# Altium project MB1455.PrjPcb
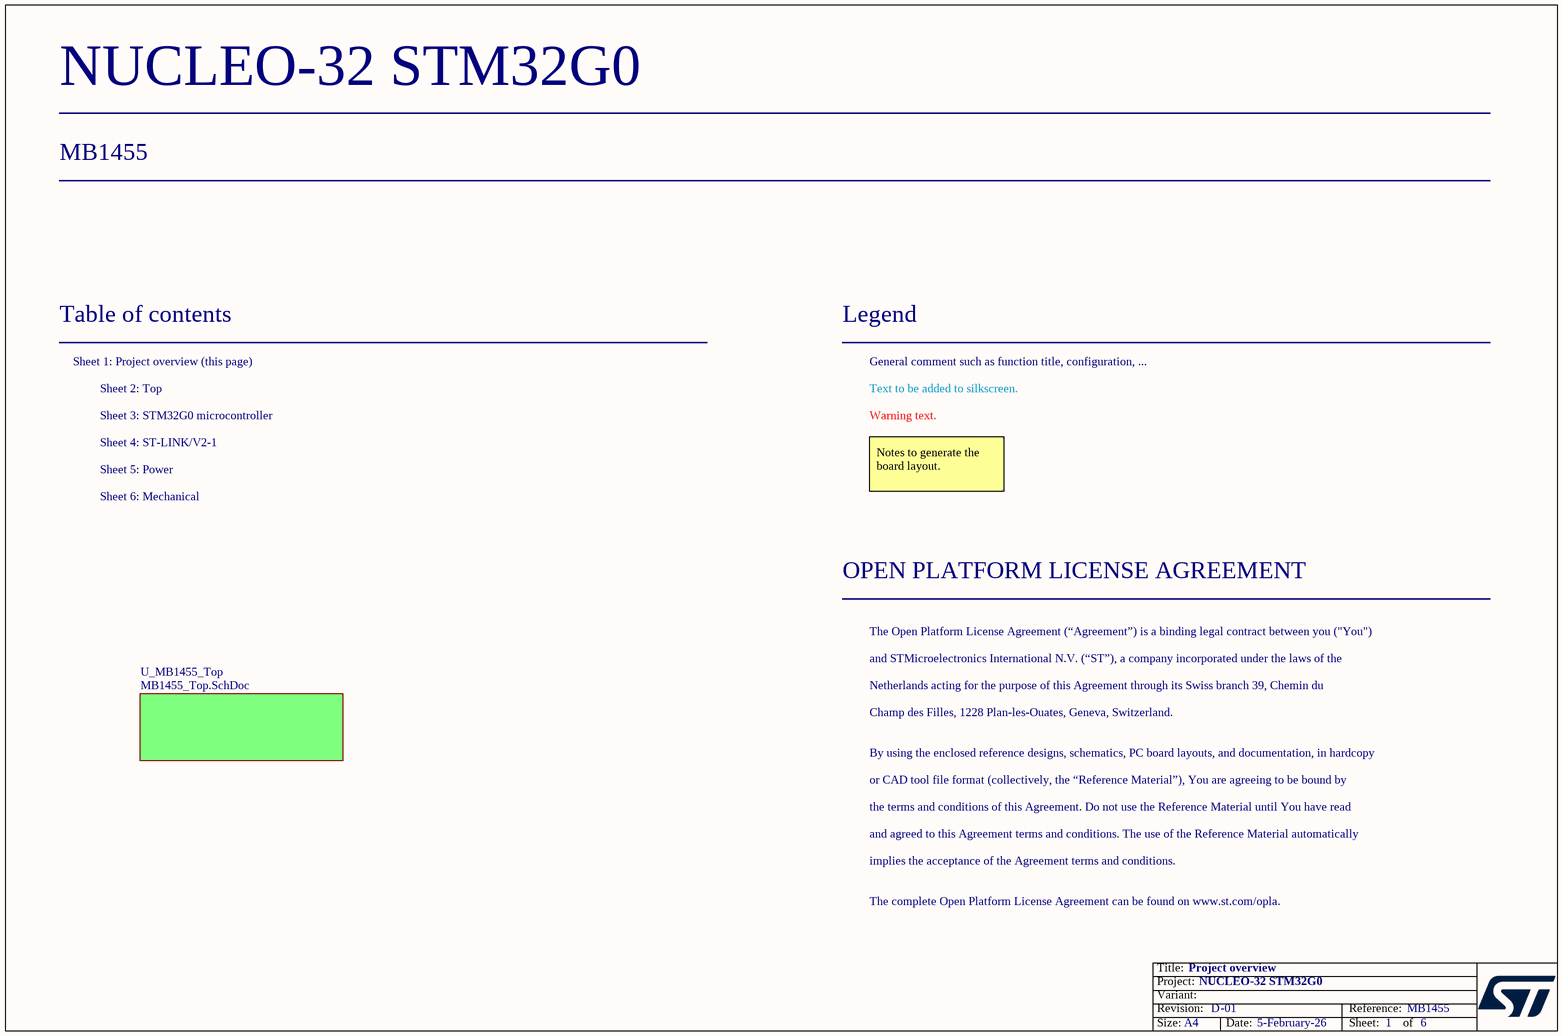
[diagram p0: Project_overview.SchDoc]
Board_Assembly_Revision: 01; Board_Document_Date: 5-February-26; Board_Name: NUCLEO-32 STM32G0; Board_PCB_Revision: D; Board_Reference: MB1455
6 sheets, 97 parts. Net scope: flat (ports and power ports of the same name join across sheets).
Board file: MB1455.PcbDoc
Sheets:
  Project_overview.SchDoc
    U_MB1455_Top = MB1455_Top.SchDoc
      U_Power = Power.SchDoc
      Mechanical = Mechanical.SchDoc
      U_ST_LINK_V2-1 = ST_LINK_V2-1.SCHDOC
      U_STM32G0_microcontroller = STM32G0_microcontroller.SchDoc

## Sheet Project_overview.SchDoc: Project overview
size A4; Date: Not used; ApprovedBy: Not used; CheckedBy: Not used; Author: Not used; CompanyName: STMicroelectronics; DrawnBy: Not used; Engineer: Not used; Organization: Not used; Address1: Not used; Address2: Not used; Address3: Not used; Address4: Not used; DocumentNumber: Not used; Revision: Not used; SheetNumber: 1; SheetTotal: 6

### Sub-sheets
U_MB1455_Top = MB1455_Top.SchDoc: no entries

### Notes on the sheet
- Table of contents
- Sheet 1: Project overview (this page)
- Legend
- General comment such as function title, configuration, ...
- Sheet 2: Top
- Sheet 4: ST-LINK/V2-1
- Sheet 3: STM32G0 microcontroller
- Text to be added to silkscreen.
- Warning text.
- Sheet 5: Power
- Sheet 6: Mechanical
- Notes to generate the board layout.
- OPEN PLATFORM LICENSE AGREEMENT
- The Open Platform License Agreement (“Agreement”) is a binding legal contract between you ("You")
- and STMicroelectronics International N.V. (“ST”), a company incorporated under the laws of the
- Netherlands acting for the purpose of this Agreement through its Swiss branch 39, Chemin du
- Champ des Filles, 1228 Plan-les-Ouates, Geneva, Switzerland.
- By using the enclosed reference designs, schematics, PC board layouts, and documentation, in hardcopy
- or CAD tool file format (collectively, the “Reference Material”), You are agreeing to be bound by
- the terms and conditions of this Agreement. Do not use the Reference Material until You have read
- and agreed to this Agreement terms and conditions. The use of the Reference Material automatically
- implies the acceptance of the Agreement terms and conditions.
- The complete Open Platform License Agreement can be found on www.st.com/opla.

## Sheet MB1455_Top.SchDoc: Top hierarchical view
size A4; Date: Not used; ApprovedBy: Not used; CheckedBy: Not used; Author: Not used; CompanyName: STMicroelectronics; DrawnBy: Not used; Engineer: Not used; Organization: Not used; Address1: Not used; Address2: Not used; Address3: Not used; Address4: Not used; DocumentNumber: Not used; Revision: A-01-P3; SheetNumber: 2; SheetTotal: 6
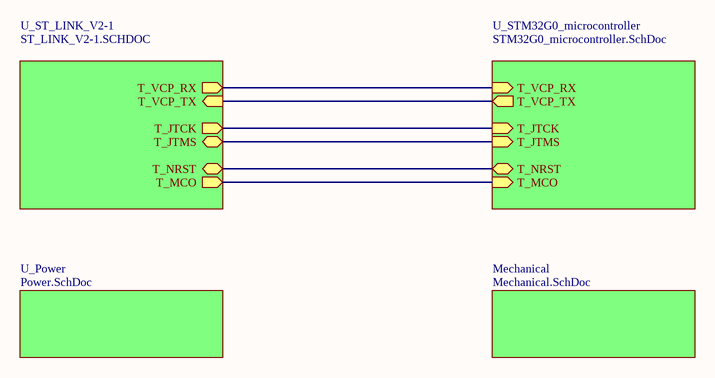
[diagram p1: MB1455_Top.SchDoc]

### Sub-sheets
Mechanical = Mechanical.SchDoc: no entries
U_Power = Power.SchDoc: no entries
U_ST_LINK_V2-1 = ST_LINK_V2-1.SCHDOC: T_VCP_RX (out), T_VCP_TX (in), T_JTMS (bidir), T_JTCK (out), T_NRST (bidir), T_MCO (out)
U_STM32G0_microcontroller = STM32G0_microcontroller.SchDoc: T_NRST (bidir), T_JTCK (in), T_JTMS (in), T_VCP_RX (in), T_VCP_TX (out), T_MCO (in)

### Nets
(unnamed): sheet U_ST_LINK_V2-1/T_VCP_RX, sheet U_STM32G0_microcontroller/T_VCP_RX
(unnamed): sheet U_ST_LINK_V2-1/T_VCP_TX, sheet U_STM32G0_microcontroller/T_VCP_TX  [a separate net that carries the same name]
(unnamed): sheet U_ST_LINK_V2-1/T_JTMS, sheet U_STM32G0_microcontroller/T_JTMS  [a separate net that carries the same name]
(unnamed): sheet U_ST_LINK_V2-1/T_JTCK, sheet U_STM32G0_microcontroller/T_JTCK  [a separate net that carries the same name]
(unnamed): sheet U_ST_LINK_V2-1/T_NRST, sheet U_STM32G0_microcontroller/T_NRST  [a separate net that carries the same name]
(unnamed): sheet U_ST_LINK_V2-1/T_MCO, sheet U_STM32G0_microcontroller/T_MCO  [a separate net that carries the same name]

## Sheet Power.SchDoc: Power
size A4; Date: Not used; ApprovedBy: Not used; CheckedBy: Not used; Author: Not used; CompanyName: STMicroelectronics; DrawnBy: Not used; Engineer: Not used; Organization: Not used; Address1: Not used; Address2: Not used; Address3: Not used; Address4: Not used; DocumentNumber: Not used; Revision: Not used; SheetNumber: 5; SheetTotal: 6
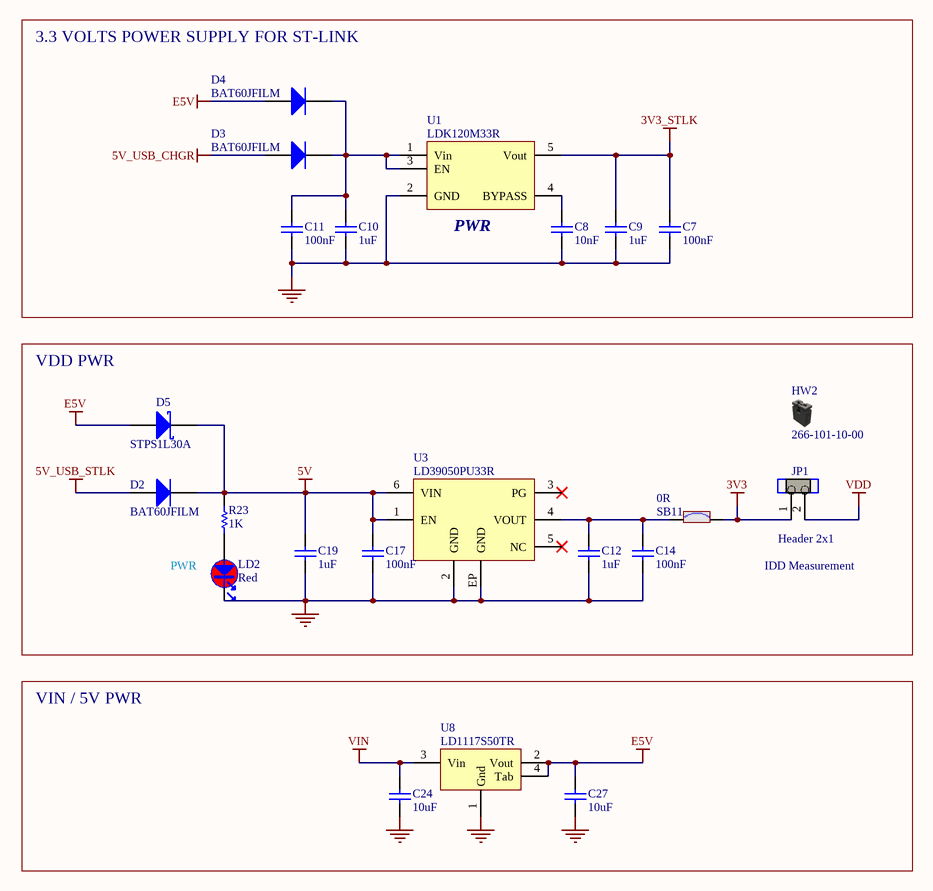
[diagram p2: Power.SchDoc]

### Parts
C7  value 100nF  [C0402]  (hidden comment: Capacitor)
C8  value 10nF  [C0402]  (hidden comment: Capacitor)
C9  value 1uF  [C0402]  (hidden comment: Capacitor)
C10  value 1uF  [C0402]  (hidden comment: Capacitor)
C11  value 100nF  [C0402]  (hidden comment: Capacitor)
C12  value 1uF  [C0402]  (hidden comment: Capacitor)
C14  value 100nF  [C0402]  (hidden comment: Capacitor)
C17  value 100nF  [C0402]  (hidden comment: Capacitor)
C19  value 1uF  [C0402]  (hidden comment: Capacitor)
C24  value 10uF  [C0805]  (hidden comment: Capacitor)
C27  value 10uF  [C0805]  (hidden comment: Capacitor)
D2  BAT60JFILM  [DIO_SOD323]
D3  BAT60JFILM  [DIO_SOD323]
D4  BAT60JFILM  [DIO_SOD323]
D5  value STPS1L30A  [DIO_SMA_1A_2K]  (hidden comment: STPS1L40M)
HW2  value 266-101-10-00  (hidden comment: Shunt Black 1.27mm 266-101-10-00)  (mechanical)
JP1  value Header 2x1  [CON_WP_707-2-02-2-20-00]  (hidden comment: Jumper_Header1.27 2x1 Fitted)
LD2  value Red  [LED_0603_VISHAY_VLMS1300-GS08_RED_1A2K_H0P8]  (hidden comment: LED_red)
R23  value 1K  [R0402]  (hidden comment: Resistor)
SB11  value 0R  [SOLDER-BRIDGE_R0603-0R]  (hidden comment: SB_ON)
U1  LDK120M33R  [REG_SOT23-5L]
U3  LD39050PU33R  [ICC_DFN6-EPAD_3X3_P095]
U8  LD1117S50TR  [REG_SOT223-TAB]

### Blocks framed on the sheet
VDD PWR: C12 C14 C17 C19 D2 D5 HW2 JP1 LD2 R23 SB11 U3
VIN / 5V PWR: C24 C27 U8

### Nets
3V3: JP1.1 SB11.2
3V3_STLK: C7.2 C9.2 U1.5(Vout)
5V: C17.2 C19.2 D2.2(K) D5.2(K) R23.2 U3.1(EN) U3.6(VIN)
5V_USB_CHGR: D3.1(A)
5V_USB_STLK: D2.1(A)
E5V: C27.2 D4.1(A) D5.1(A) U8.2(Vout) U8.4(Tab)
GND: C7.1 C8.1 C9.1 C10.1 C11.1 C12.1 C14.1 C17.1 C19.1 C24.1 C27.1 LD2.2 U1.2(GND) U3.2(GND) U3.EP(GND) U8.1(Gnd)
VDD: JP1.2
VIN: C24.2 U8.3(Vin)
NetC8_2: C8.2 U1.4(BYPASS)
NetC10_2: C10.2 C11.2 D3.2(K) D4.2(K) U1.1(Vin) U1.3(EN)
NetC12_2: C12.2 C14.2 SB11.1 U3.4(VOUT)
NetLD2_1: LD2.1 R23.1

Not connected (* = marked no-connect by the designer): U3 3(PG)* 5(NC)*

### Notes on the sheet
- 3.3 VOLTS POWER SUPPLY FOR ST-LINK
- (near U1) PWR
- PWR
- IDD Measurement

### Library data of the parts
C7 C11 C14 C17 = MCD-00006: Capacitor, MLCC, 100nF, 16V, X7R, +/-10%, 0402, T=0.5mm; Manufacturer_Part_Number: CC0402KRX7R7BB104; Manufacturer: YAGEO; Part_Preference: Recommended; Partial_Alternate_Internal_Part_Number: MCD-03299; Component_Country_Of_Origin: China; ID: 2474; Order_Code_RS: 9402047; ShowFields: YES
C8 = MCD-00011: Capacitor, MLCC, 10nF, 16V, X7R, 10%, 0402, T=0.5mm; Manufacturer_Part_Number: CC0402KRX7R7BB103; Manufacturer: YAGEO; Part_Preference: Recommended; Provided_By: SUBCO; ECCN_US: EAR99; ECCN_EU: NEC; Component_Country_Of_Origin: China; ID: 2469; Order_Code_RS: 3019275; ShowFields: YES
C9 C10 C12 C19 = MCD-00095: Capacitor, MLCC, 1uF, 6V3, X5R, 10%, 0402, T=0,5mm; Manufacturer_Part_Number: GRM155R61E105KA12; Manufacturer: MURATA; Alternate_Manufacturer_Part_Number: GRM155R60J105KE19; Part_Preference: Recommended; Partial_Alternate_Internal_Part_Number: MCD-04188; Provided_By: SUBCO; ECCN_US: EAR99; ECCN_EU: NEC; Component_Country_Of_Origin: Japan°°; ID: 2772; Order_Code_RS: 2218855; ShowFields: YES
C24 C27 = MCD-00014: Capacitor, MLCC, 10uF, 25V, X5R, 10%, 0805, T=0,85mm; Manufacturer_Part_Number: CC0805KRX5R8BB106; Manufacturer: YAGEO; Full_Alternate_Internal_Part_Number: MCD-02385; Part_Preference: Recommended; Partial_Alternate_Internal_Part_Number: MCD-03053; Provided_By: SUBCO; ECCN_US: EAR99; ECCN_EU: NEC; Component_Country_Of_Origin: China; ID: 2468; ShowFields: YES
D2-D4 = MCD-00034: Part_Type: Diode; Manufacturer: STMICROELECTRONICS; BMS_Part_Number: 9151097; Manufacturer_HQ_COO: EU; Part_Preference: Recommended; ECCN_US: EAR99; ECCN_EU: NEC; Provided_By: SUBCO with ST control; Component_Country_Of_Origin: China; ID: 2483; Order_Code_RS: 714-6879; ShowFields: YES
D5 = MCD-01059: LOW DROP POWER SCHOTTKY RECTIFIER 1A 30V VF=0.3V; Part_Type: Diode; Manufacturer: STMICROELECTRONICS; BMS_Part_Number: 9151096; Manufacturer_HQ_COO: EU; Part_Preference: Recommended; Provided_By: SUBCO with ST control; ECCN_US: EAR99; ECCN_EU: NEC; Component_Country_Of_Origin: China; ID: 2966; Order_Code_RS: 485-8061; ShowFields: YES
HW2 = MCD-01409: SHUNT 1.27mm BLACK; Part_Type: Misc; Manufacturer: W&P PRODUCTS; Alternate_Manufacturer_Part_Number: M50-1900005; Alternate_Manufacturer: HARWIN; Manufacturer_HQ_COO: Unknown; Part_Preference: Recommended; Partial_Alternate_Internal_Part_Number: MCD-04276; Provided_By: SUBCO; Component_Country_Of_Origin: China; ID: 3509; ShowFields: YES
JP1 = MCD-01428: Header, 2x1, 1,27mm, Right Angled, Single Row, Height 3.05mm/1.27mm; Part_Type: Connector; Manufacturer_Part_Number: 707-2-02-2-20-00; Manufacturer: W&P PRODUCTS; Part_Preference: Recommended; Partial_Alternate_Internal_Part_Number: MCD-04275; Provided_By: SUBCO; Component_Country_Of_Origin: China; ID: 3528; ShowFields: YES
LD2 = MCD-02787: LED, Red, 1V7 to 2V2, 5mA, 0603; Manufacturer_Part_Number: 19-217/R6C-AL1M2VY/6T; Manufacturer: EVERLIGHT; Part_Type: Display; Part_Preference: Recommended; Full_Alternate_Internal_Part_Number: MCD-02401; Partial_Alternate_Internal_Part_Number: MCD-00586; Component_Country_Of_Origin: China; ID: 4899; ShowFields: YES
R23 = MCD-00061: Resistor,1K,0402,1%,1/16W; Manufacturer_Part_Number: RC0402FR-071KL; Manufacturer: YAGEO; Part_Preference: Recommended; Provided_By: SUBCO; ECCN_US: EAR99; ECCN_EU: NEC; Component_Country_Of_Origin: China; ID: 2532; Order_Code_RS: 9239235; ShowFields: YES
SB11 = MCD-00071: Solder Bridge ON; Part_Type: Resistor; Manufacturer_Part_Number: RC0603JR-070RL; Manufacturer: YAGEO; Manufacturer_HQ_COO: Unknown; Part_Preference: Recommended; Provided_By: SUBCO; Component_Country_Of_Origin: China; ID: 2521; Order_Code_RS: 199-5647; ShowFields: YES
U1 = MCD-00663: 200 mA low quiescent current very low noise LDO; Part_Type: IC; Manufacturer: STMICROELECTRONICS; BMS_Part_Number: 9176330; Manufacturer_HQ_COO: EU; Part_Preference: Recommended; Partial_Alternate_Internal_Part_Number: MCD-03279; ECCN_US: EAR99; ECCN_EU: NEC; Provided_By: SUBCO with ST control; Component_Country_Of_Origin: China; ID: 3082; Order_Code_RS: 188-9202; ShowFields: YES
U3 = MCD-00215: Low quiescent current and low noise voltage regulators; Manufacturer: STMICROELECTRONICS; Part_Type: IC; BMS_Part_Number: 9176126; Part_Preference: Recommended; Provided_By: SUBCO with ST control; ECCN_US: EAR99; ECCN_EU: NEC; Component_Country_Of_Origin: Malaysia; ID: 2654; Order_Code_RS: 196-1948; ShowFields: YES
U8 = MCD-00088: IC REG LDO 5V 0.8A SOT223; Manufacturer: STMICROELECTRONICS; BMS_Part_Number: 9176133; Manufacturer_HQ_COO: EU; Part_Preference: Recommended; Provided_By: SUBCO with ST control; ECCN_US: EAR99; ECCN_EU: NEC; Component_Country_Of_Origin: China; ID: 2503; Order_Code_RS: 165-7748; ShowFields: YES

## Sheet Mechanical.SchDoc: Mechanical
size A4; Date: Not used; ApprovedBy: Not used; CheckedBy: Not used; Author: Not used; CompanyName: STMicroelectronics; DrawnBy: Not used; Engineer: Not used; Organization: Not used; Address1: Not used; Address2: Not used; Address3: Not used; Address4: Not used; DocumentNumber: Not used; Revision: Not used; SheetNumber: 6; SheetTotal: 6
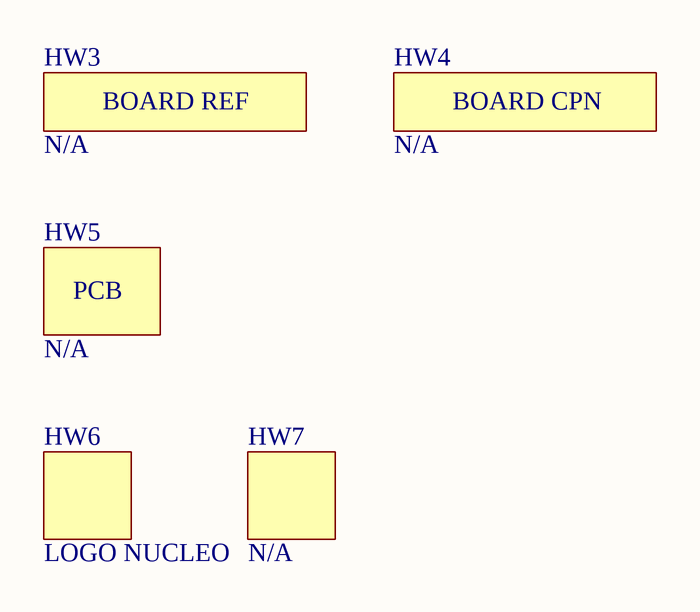
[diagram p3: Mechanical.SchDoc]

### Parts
HW3  STICKER_BOARD_REF  [STICKER_25X9]  (value not drawn)  (no BOM)
HW4  STICKER_BOARD_CPN  [STICKER_25X9]  (value not drawn)  (no BOM)
HW5  PCB  (value not drawn)  (no BOM)
HW6  value LOGO NUCLEO  [LOGO_NUCLEO]  (hidden comment: Logo)  (no BOM)
HW7  Logo  [LOGO_ST]  (value not drawn)  (no BOM)

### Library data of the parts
HW3 = MCD-00235: Sticker to mention board reference + serial number; Part_Type: Misc; Part_Preference: Recommended; Provided_By: SUBCO; Component_Country_Of_Origin: Unknown; ID: 2632; ShowFields: YES
HW4 = MCD-00547: Sticker to mention board CPN code; Part_Type: Misc; Part_Preference: Recommended; Provided_By: SUBCO; Component_Country_Of_Origin: Unknown; ID: 3197; ShowFields: YES
HW5 = MCD-00216: PCB, xxxx for PCB number, Y for PCB revision; Part_Type: Misc; Part_Preference: Forbidden; Provided_By: SUBCO; Component_Country_Of_Origin: Unknown; ID: 2653; ShowFields: YES
HW6 = MCD-00636: NUCLEO logo footprint for PCB; Part_Type: Accessory; Part_Preference: Forbidden; Component_Country_Of_Origin: Unknown; ID: 3110; ShowFields: YES
HW7 = MCD-00625: STMicroelectronics logo footprint for PCB; Part_Type: Misc; Part_Preference: Forbidden; Component_Country_Of_Origin: Unknown; ID: 3117; ShowFields: YES

## Sheet ST_LINK_V2-1.SCHDOC: ST_LINK_V2-1
size A4; Date: Not used; ApprovedBy: Not used; CheckedBy: Not used; Author: Not used; CompanyName: STMicroelectronics; DrawnBy: Not used; Engineer: Not used; Organization: Not used; Address1: Not used; Address2: Not used; Address3: Not used; Address4: Not used; DocumentNumber: Not used; Revision: Not used; SheetNumber: 4; SheetTotal: 6
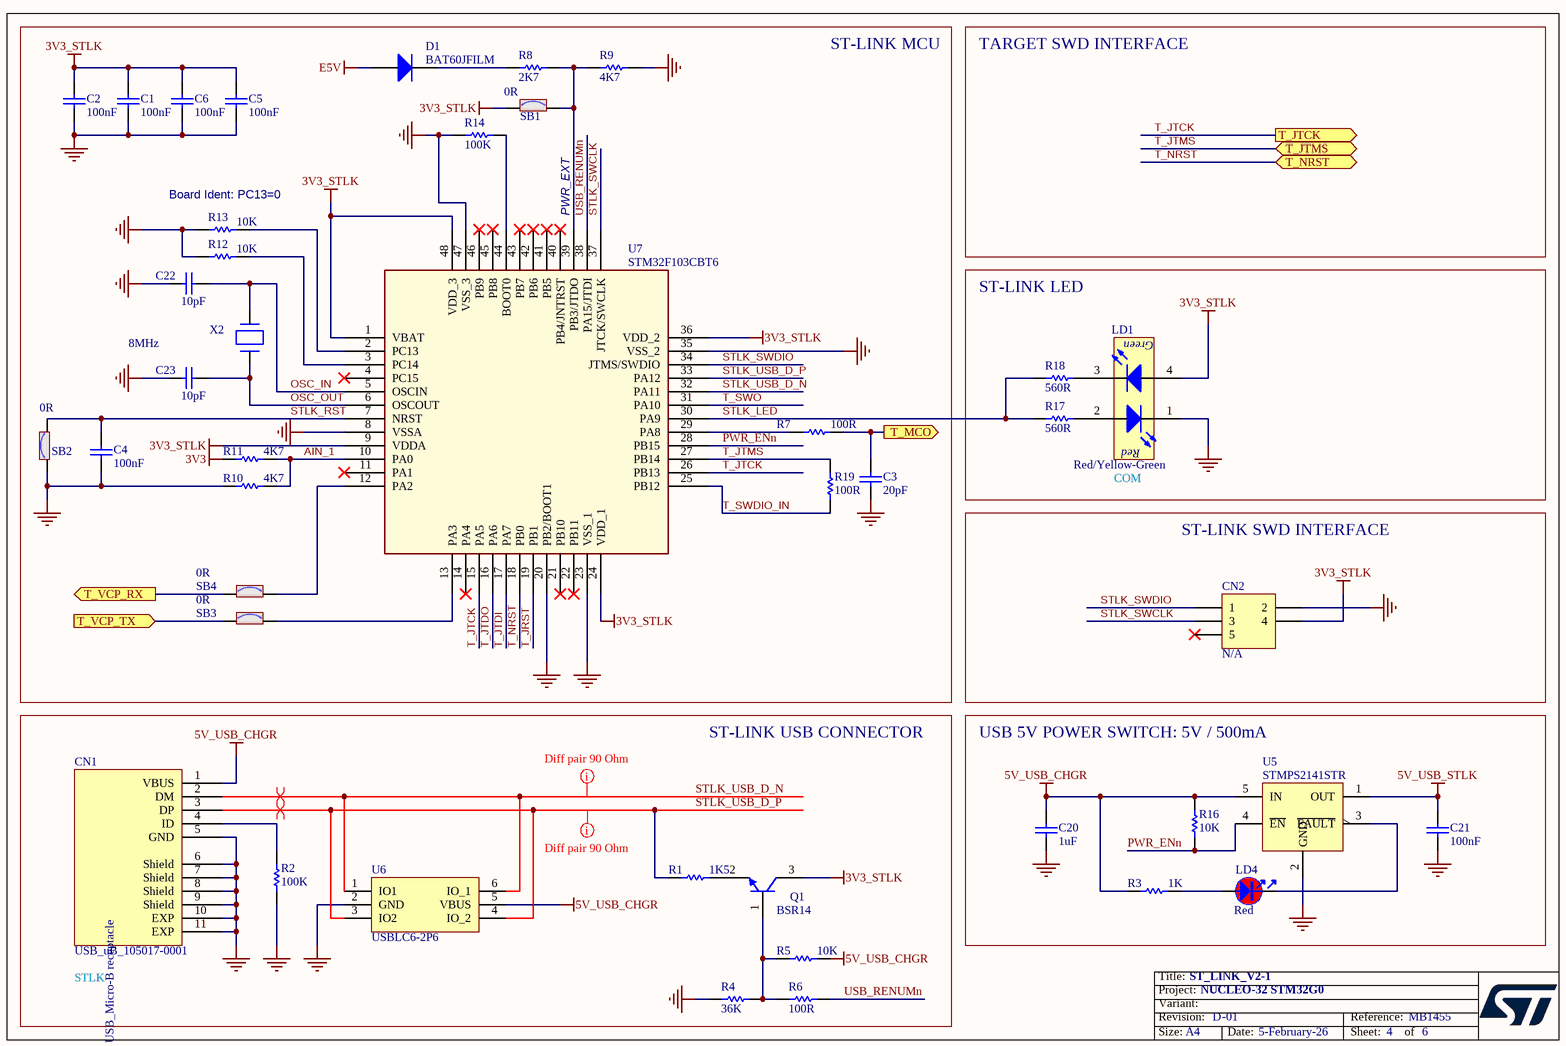
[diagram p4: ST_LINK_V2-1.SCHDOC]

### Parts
C1  value 100nF  [C0402]  (hidden comment: Capacitor)
C2  value 100nF  [C0402]  (hidden comment: Capacitor)
C3  value 20pF  [C0402]  (hidden comment: Capacitor)
C4  value 100nF  [C0402]  (hidden comment: Capacitor)
C5  value 100nF  [C0402]  (hidden comment: Capacitor)
C6  value 100nF  [C0402]  (hidden comment: Capacitor)
C20  value 1uF  [C0402]  (hidden comment: Capacitor)
C21  value 100nF  [C0402]  (hidden comment: Capacitor)
C22  value 10pF  [C0402]  (hidden comment: Capacitor)
C23  value 10pF  [C0402]  (hidden comment: Capacitor)
CN1  value USB_uB_105017-0001  [CON_USBMICROB_MOLEX_105017-0001_H2P90]  (hidden comment: USB_uB_105017.0001)
CN2  Header STLINK  [HDR_1x5_2R54_V_M]  (value not drawn)
D1  BAT60JFILM  [DIO_SOD323]
LD1  value Red/Yellow-Green  [LED_BI-GR_HSMF-A201-A00J1]  (hidden comment: LD_BICOLOR_CMS)
LD4  value Red  [LED_0603_VISHAY_VLMS1300-GS08_RED_1A2K_H0P8]  (hidden comment: LED_red)
Q1  value BSR14  [NPN_SOT23]  (hidden comment: 9013-SOT23)
R1  value 1K5  [R0402]  (hidden comment: Resistor)
R2  value 100K  [R0402]  (hidden comment: Resistor)
R3  value 1K  [R0402]  (hidden comment: Resistor)
R4  value 36K  [R0402]  (hidden comment: Resistor)
R5  value 10K  [R0402]  (hidden comment: Resistor)
R6  value 100R  [R0402]  (hidden comment: Resistor)
R7  value 100R  [R0402]  (hidden comment: Resistor)
R8  value 2K7  [R0402]  (hidden comment: Resistor)
R9  value 4K7  [R0402]  (hidden comment: Resistor)
R10  value 4K7  [R0402]  (hidden comment: Resistor)
R11  value 4K7  [R0402]  (hidden comment: Resistor)
R12  value 10K  [R0402]  (hidden comment: Resistor)
R13  value 10K  [R0402]  (hidden comment: Resistor)
R14  value 100K  [R0402]  (hidden comment: Resistor)
R16  value 10K  [R0402]  (hidden comment: Resistor)
R17  value 560R  [R0402]  (hidden comment: Resistor)
R18  value 560R  [R0402]  (hidden comment: Resistor)
R19  value 100R  [R0402]  (hidden comment: Resistor)
SB1  value 0R  [SOLDER-BRIDGE_R0603-0R]  (hidden comment: SB_ON)
SB2  value 0R  [SOLDER-BRIDGE_R0603-0R]  (hidden comment: SB_ON)
SB3  value 0R  [SOLDER-BRIDGE_R0603-0R]  (hidden comment: SB_ON)
SB4  value 0R  [SOLDER-BRIDGE_R0603-0R]  (hidden comment: SB_ON)
U5  STMPS2141STR  [MOS_SOT23-5L]
U6  USBLC6-2P6  [ESD_SOT666]
U7  STM32F103CBT6  [ICC_LQFP48_7X7_P050]
X2  value 8MHz  [CRY_NX3225GD_2P]  (hidden comment: XTAL_2_PINS)

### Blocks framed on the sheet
ST-LINK MCU: C1-C6 C22 C23 D1 R7-R14 R19 SB1-SB4 U7 X2
ST-LINK LED: LD1 R17 R18
ST-LINK SWD INTERFACE: CN2
ST-LINK USB CONNECTOR: CN1 Q1 R1 R2 R4-R6 U6
USB 5V POWER SWITCH: 5V / 500mA: C20 C21 LD4 R3 R16 U5

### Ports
T_JTCK (out), T_JTMS (bidir), T_MCO (out), T_NRST (bidir), T_VCP_RX (out), T_VCP_TX (in)

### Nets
3V3: R11.1
3V3_STLK: C1.2 C2.2 C5.2 C6.2 CN2.4 LD1.4(YellowGreen_anode) Q1.3(C) SB1.1 U7.1(VBAT) U7.9(VDDA) U7.24(VDD_1) U7.36(VDD_2) U7.48(VDD_3)
5V_USB_CHGR: C20.2 CN1.1(VBUS) R3.1 R5.2 R16.2 U5.5(IN) U6.5(VBUS)
5V_USB_STLK: C21.2 U5.1(OUT)
E5V: D1.1(A)
GND: C1.1 C2.1 C3.1 C4.1 C5.1 C6.1 C20.1 C21.1 C22.1 C23.1 CN1.5(GND) CN1.6(Shield) CN1.7(Shield) CN1.8(Shield) CN1.9(Shield) CN1.10(EXP) CN1.11(EXP) CN2.2 LD1.1(RED_cathode) R2.1 R4.1 R9.2 R10.1 R12.1 R13.1 R14.1 SB2.1 U5.2(GND) U6.2(GND) U7.8(VSSA) U7.20(PB2/BOOT1) U7.23(VSS_1) U7.35(VSS_2) U7.47(VSS_3)
AIN_1: R10.2 R11.2 U7.10(PA0)
OSC_IN: C22.2 U7.5(OSCIN) X2.1(X1)
OSC_OUT: C23.2 U7.6(OSCOUT) X2.2(X2)
PWR_ENn: R16.1 U5.4(~{EN}) U7.28(PB15)
STLK_LED: R17.1 R18.1 U7.30(PA9)
STLK_RST: C4.2 SB2.2 U7.7(NRST)
STLK_SWCLK: CN2.3 U7.37(JTCK/SWCLK)
STLK_SWDIO: CN2.1 U7.34(JTMS/SWDIO)
STLK_USB_D_N: CN1.2(DM) U6.1(IO1) U6.6(IO_1) U7.32(PA11)
STLK_USB_D_P: CN1.3(DP) R1.1 U6.3(IO2) U6.4(IO_2) U7.33(PA12)
T_JRST: U7.19(PB1)
T_JTCK: U7.15(PA5) U7.26(PB13) ; port T_JTCK
T_JTDI: U7.17(PA7)
T_JTDO: U7.16(PA6)
T_JTMS: R19.2 U7.27(PB14) ; port T_JTMS
T_NRST: U7.18(PB0) ; port T_NRST
T_SWDIO_IN: R19.1 U7.25(PB12)
T_SWO: U7.31(PA10)
USB_RENUMn: R6.2 U7.38(PA15/JTDI)
NetC3_2: C3.2 R7.2 ; port T_MCO
NetCN1_4: CN1.4(ID) R2.2
NetD1_2: D1.2(K) R8.1
NetLD1_2: LD1.2(Red_anode) R17.2
NetLD1_3: LD1.3(YellowGreen_cathode) R18.2
NetLD4_1: LD4.1 R3.2
NetLD4_2: LD4.2 U5.3(~{FAULT})
NetQ1_1: Q1.1(B) R4.2 R5.1 R6.1
NetQ1_2: Q1.2(E) R1.2
NetR7_1: R7.1 U7.29(PA8)
NetR8_2: R8.2 R9.1 SB1.2 U7.39(PB3/JTDO)
NetR12_2: R12.2 U7.3(PC14)
NetR13_2: R13.2 U7.2(PC13)
NetR14_2: R14.2 U7.44(BOOT0)
NetSB3_1: SB3.1 ; port T_VCP_TX
NetSB3_2: SB3.2 U7.13(PA3)
NetSB4_1: SB4.1 ; port T_VCP_RX
NetSB4_2: SB4.2 U7.12(PA2)

Not connected (* = marked no-connect by the designer): CN2 5*; U7 4(PC15)* 11(PA1)* 14(PA4)* 21(PB10)* 22(PB11)* 40(PB4/JNTRST)* 41(PB5)* 42(PB6)* 43(PB7)* 45(PB8)* 46(PB9)*

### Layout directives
differential pair: STLK_USB_D_N, STLK_USB_D_P
mark named Diff pair 90 Ohm: STLK_USB_D_N, STLK_USB_D_P

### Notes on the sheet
- TARGET SWD INTERFACE
- (near R13) Board Ident: PC13=0
- PWR_EXT
- COM
- STLK

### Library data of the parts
C1 C2 C4-C6 C21 = MCD-00006: as C7 on sheet Power
C3 = MCD-00016: Capacitor, MLCC, 20pF, 50V, NPO, 5%, 0402, T=0,5mm; Manufacturer_Part_Number: CC0402JRNPO9BN200; Manufacturer: YAGEO; Part_Preference: Recommended; Provided_By: SUBCO; ECCN_US: EAR99; ECCN_EU: NEC; Component_Country_Of_Origin: China; ID: 2479; ShowFields: YES
C20 = MCD-00095: as C9 on sheet Power
C22 C23 = MCD-00015: Capacitor, MLCC, 10pF, 50V, NPO, 5%, 0402, T=0,5mm; Manufacturer_Part_Number: CC0402JRNPO9BN100; Manufacturer: YAGEO; Part_Preference: Recommended; Provided_By: SUBCO; ECCN_US: EAR99; ECCN_EU: NEC; Component_Country_Of_Origin: China; ID: 2465; Order_Code_RS: 3019160RL; ShowFields: YES
CN1 = MCD-00028: USB-MICRO-B, 0.65mm, RA, SMT, Bottom Mount,; Part_Type: Connector; Manufacturer_Part_Number: 1050170001; Manufacturer: MOLEX; Part_Preference: Recommended; Partial_Alternate_Internal_Part_Number: MCD-04277; Provided_By: SUBCO; Component_Country_Of_Origin: Unknown; ID: 2489; Order_Code_RS: 2293836; ShowFields: YES
CN2 = MCD-01399: Header 5 pads for ST-LINK prog. Not fitted; Part_Type: Misc; Part_Preference: Forbidden; Provided_By: SUBCO; Component_Country_Of_Origin: Unknown; ID: 3499; ShowFields: YES
D1 = MCD-00034: Manufacturer: STMICROELECTRONICS; Part_Type: Diode; BMS_Part_Number: 9151097; Manufacturer_HQ_COO: EU; Part_Preference: Recommended; ECCN_US: EAR99; ECCN_EU: NEC; Provided_By: SUBCO with ST control; Component_Country_Of_Origin: China; ID: 2483; Order_Code_RS: 714-6879; ShowFields: YES
LD1 = MCD-02402: LED Bicolor, Red/Yellow-Green , 2V, 20mA, 4-PLCC; Part_Type: Display; Manufacturer_Part_Number: 67-22SURSYGC/S530-A2/TR8; Manufacturer: EVERLIGHT; Full_Alternate_Internal_Part_Number: MCD-00051, MCD-02631; Part_Preference: Not recommended; ID: 4508; ShowFields: YES
LD4 = MCD-02787: LED, Red, 1V7 to 2V2, 5mA, 0603; Part_Type: Display; Manufacturer_Part_Number: 19-217/R6C-AL1M2VY/6T; Manufacturer: EVERLIGHT; Part_Preference: Recommended; Full_Alternate_Internal_Part_Number: MCD-02401; Partial_Alternate_Internal_Part_Number: MCD-00586; Component_Country_Of_Origin: China; ID: 4899; ShowFields: YES
Q1 = MCD-00073: NPN Bipolar Transistor; Manufacturer: ON SEMICONDUCTOR; Alternate_Manufacturer_Part_Number: MMBT2222LT1G / MMBT2222ALT1G / MMBT2222ALT3G; Part_Preference: Recommended; Partial_Alternate_Internal_Part_Number: MCD-01737, MCD-03305, MCD-02988; ECCN_US: EAR99; ECCN_EU: NEC; Provided_By: SUBCO; Component_Country_Of_Origin: Unknown; ID: 2519; ShowFields: YES
R1 = MCD-00068: Resistor,1K5,0402,1%,1/16W; Manufacturer_Part_Number: RC0402FR-071K5L; Manufacturer: YAGEO; Part_Preference: Recommended; Provided_By: SUBCO; ECCN_US: EAR99; ECCN_EU: NEC; Component_Country_Of_Origin: China; ID: 2524; Order_Code_RS: 9239251; ShowFields: YES
R2 R14 = MCD-00059: Resistor,100K,0402,1%,1/16W; Manufacturer_Part_Number: RC0402FR-07100KL; Manufacturer: YAGEO; Alternate_Manufacturer_Part_Number: RT0402FRE07100KL; Part_Preference: Recommended; Partial_Alternate_Internal_Part_Number: MCD-03301; Provided_By: SUBCO; ECCN_US: EAR99; ECCN_EU: NEC; Component_Country_Of_Origin: China; ID: 2533; Order_Code_RS: 2421891; ShowFields: YES
R3 = MCD-00061: as R23 on sheet Power
R4 = MCD-00069: Resistor,36K,0402,1%,1/16W; Manufacturer_Part_Number: RC0402FR-0736KL; Manufacturer: YAGEO; Part_Preference: Recommended; Provided_By: SUBCO; ECCN_US: EAR99; ECCN_EU: NEC; Component_Country_Of_Origin: China; ID: 2523; Order_Code_RS: 1458788; ShowFields: YES
R5 R12 R13 R16 = MCD-00053: Resistor,10K,0402,1%,1/16W; Manufacturer_Part_Number: RC0402FR-0710KL; Manufacturer: YAGEO; BMS_Part_Number: 9131590; Part_Preference: Recommended; Provided_By: SUBCO; ECCN_US: EAR99; ECCN_EU: NEC; Component_Country_Of_Origin: China; ID: 2539; Order_Code_RS: 9239359; ShowFields: YES
R6 R7 R19 = MCD-00067: Resistor,100R,0402,1%,1/16W; Manufacturer_Part_Number: RC0402FR-07100RL; Manufacturer: YAGEO; Part_Preference: Recommended; Provided_By: SUBCO; ECCN_US: EAR99; ECCN_EU: NEC; Component_Country_Of_Origin: China; ID: 2527; Order_Code_RS: 9239111; ShowFields: YES
R8 = MCD-00055: Resistor,2K7,0402,1%,1/16W; Manufacturer_Part_Number: RC0402FR-072K7L; Manufacturer: YAGEO; Part_Preference: Recommended; Provided_By: SUBCO; ECCN_US: EAR99; ECCN_EU: NEC; Component_Country_Of_Origin: China; ID: 2535; Order_Code_RS: 9239286; ShowFields: YES
R9-R11 = MCD-00065: Resistor,4K7,0402,1%,1/16W; Manufacturer_Part_Number: RC0402FR-074K7L; Manufacturer: YAGEO; Alternate_Manufacturer_Part_Number: RT0402FRE074K7L; Part_Preference: Recommended; Partial_Alternate_Internal_Part_Number: MCD-03300; Provided_By: SUBCO; ECCN_US: EAR99; ECCN_EU: NEC; Component_Country_Of_Origin: China; ID: 2526; Order_Code_RS: 9239316; ShowFields: YES
R17 R18 = MCD-00489: Resistor, 560R, 0402, +/-1%, 1/16W; Manufacturer_Part_Number: RC0402FR-07560RL; Manufacturer: YAGEO; Part_Preference: Recommended; Component_Country_Of_Origin: China; ID: 2789; ShowFields: YES
SB1 SB2 = MCD-00071: Resistor, 0R, SB0603, 5%, 0.1W; Manufacturer_Part_Number: RC0603JR-070RL; Manufacturer: YAGEO; Manufacturer_HQ_COO: Unknown; Part_Preference: Recommended; Component_Country_Of_Origin: China; ID: 2521; Order_Code_RS: 199-5647; ShowFields: YES
SB3 SB4 = MCD-00071: as SB11 on sheet Power
U5 = MCD-00083: Enhanced single channel power switches with active low enable pin; Part_Type: IC; Manufacturer: STMICROELECTRONICS; Alternate_Manufacturer_Part_Number: TPS2041C; Alternate_Manufacturer: TEXAS INSTRUMENTS; BMS_Part_Number: 9159003; Manufacturer_HQ_COO: EU; Part_Preference: Recommended; ECCN_US: EAR99; ECCN_EU: NEC; Provided_By: SUBCO with ST control; Component_Country_Of_Origin: Malaysia; ID: 2509; Order_Code_RS: 880-5406; ShowFields: YES
U6 = MCD-00169: USB OTG FS ESD protection; Part_Type: Diode; Manufacturer: STMICROELECTRONICS; BMS_Part_Number: 9151057; Part_Preference: Recommended; ECCN_US: EAR99; ECCN_EU: NEC; Provided_By: SUBCO with ST control; Component_Country_Of_Origin: China; ID: 2698; Order_Code_RS: 920-6260; ShowFields: YES
U7 = MCD-00085: Medium-density performance line ARM-based 32-bit MCU with 128KB Flash; Manufacturer: STMICROELECTRONICS; Part_Type: IC; BMS_Part_Number: 9175111; Manufacturer_HQ_COO: EU; Part_Preference: Not recommended; ECCN_US: 3A991A2; ECCN_EU: NEC; Provided_By: SUBCO with ST control; Component_Country_Of_Origin: Malaysia; ID: 2507; Order_Code_RS: 402-273; ShowFields: YES
X2 = MCD-00092: Crystal 8MHz, 8pF, +-20ppm, 500ohms max,  SMD; Part_Type: Crystal_Osc; Manufacturer_Part_Number: NX3225GD-8MHz-EXS00A-CG04874; Manufacturer: NDK; BMS_Part_Number: 9157029; Part_Preference: Recommended; ECCN_US: EAR99; ECCN_EU: NEC; Provided_By: SUBCO; Component_Country_Of_Origin: China; ID: 2776; ShowFields: YES

## Sheet STM32G0_microcontroller.SchDoc: STM32G0 microcontroller
size A4; Date: Not used; ApprovedBy: Not used; CheckedBy: Not used; Author: Not used; CompanyName: STMicroelectronics; DrawnBy: Not used; Engineer: Not used; Organization: Not used; Address1: Not used; Address2: Not used; Address3: Not used; Address4: Not used; DocumentNumber: Not used; Revision: Not used; SheetNumber: 3; SheetTotal: 6
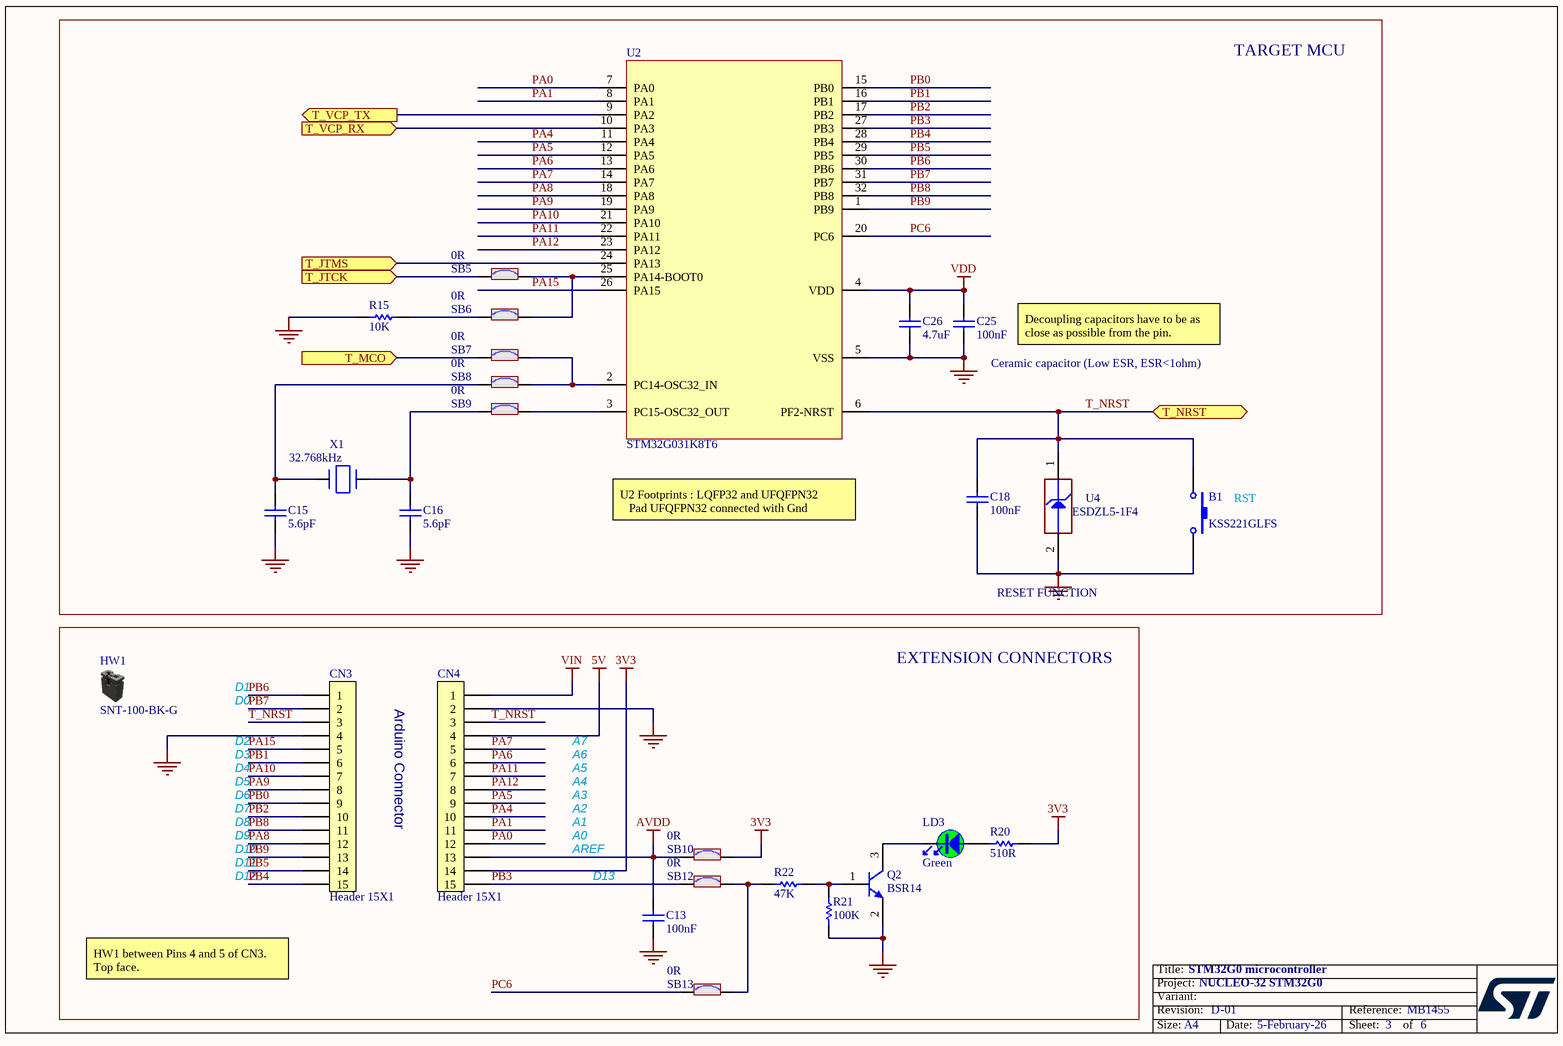
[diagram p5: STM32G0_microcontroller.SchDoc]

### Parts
B1  value KSS221GLFS  [SWI_C&K_ITT_KSS221G]  (hidden comment: SW-PB)
C13  value 100nF  [C0402]  (hidden comment: Capacitor)
C15  value 5.6pF  [C0402]  (hidden comment: Capacitor)
C16  value 5.6pF  [C0402]  (hidden comment: Capacitor)
C18  value 100nF  [C0402]  (hidden comment: Capacitor)
C25  value 100nF  [C0402]  (hidden comment: Capacitor)
C26  value 4.7uF  [C0402]  (hidden comment: Capacitor)
CN3  Header 15x1  [CON_LYCN_313115S161145]
CN4  Header 15x1  [CON_LYCN_313115S161145]
HW1  value SNT-100-BK-G  (hidden comment: Shunt Black 2.54mm)  (mechanical)
LD3  value Green  [LED_0603_GREEN]  (hidden comment: LED_green)
Q2  value BSR14  [NPN_SOT23]  (hidden comment: 9013-SOT23)
R15  value 10K  [R0402]  (hidden comment: Resistor)
R20  value 510R  [R0402]  (hidden comment: Resistor)
R21  value 100K  [R0402]  (hidden comment: Resistor)
R22  value 47K  [R0402]  (hidden comment: Resistor)
SB5  value 0R  [SOLDER-BRIDGE_R0603-0R]  (hidden comment: SB_ON)
SB6  value 0R  [SOLDER-BRIDGE_R0603-0R]  (hidden comment: SB_ON)
SB7  value 0R  [SOLDER-BRIDGE_R0603-0R]  (hidden comment: SB_ON)
SB8  value 0R  [SOLDER-BRIDGE_R0603-0R]  (hidden comment: SB_ON)
SB9  value 0R  [SOLDER-BRIDGE_R0603-0R]  (hidden comment: SB_ON)
SB10  value 0R  [SOLDER-BRIDGE_R0603-0R]  (hidden comment: SB_ON)
SB12  value 0R  [SOLDER-BRIDGE_R0603-0R]  (hidden comment: SB_ON)
SB13  value 0R  [SOLDER-BRIDGE_R0603-0R]  (hidden comment: SB_ON)
U2  value STM32G031K8T6  [ICC_LQFP32_7X7_P080__UFQFPN32-EPAD_5X5_P050__DI]  (hidden comment: STM32G031K8T6U)
U4  value ESDZL5-1F4  [ESD_0201_H0P3_1K_2A_REF2]  (hidden comment: ESD-TRANSIL)
X1  value 32.768kHz  [CRY_NX3215SA_2P]  (hidden comment: XTAL_2_PINS)

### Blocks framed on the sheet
TARGET MCU: B1 C15 C16 C18 C25 C26 R15 SB5-SB9 U2 U4 X1
EXTENSION CONNECTORS: C13 CN3 CN4 HW1 LD3 Q2 R20-R22 SB10 SB12 SB13

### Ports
T_JTCK (in), T_JTMS (in), T_MCO (in), T_NRST (bidir), T_VCP_RX (in), T_VCP_TX (out)

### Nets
3V3: CN4.14 R20.2 SB10.2
5V: CN4.4
AVDD: C13.2 CN4.13 SB10.1
GND: B1.2 C13.1 C15.1 C16.1 C18.1 C25.1 C26.1 CN3.4 CN4.2 Q2.2(E) R15.1 R21.1 U2.5(VSS) U4.2(GND)
VDD: C25.2 C26.2 U2.4(VDD)
VIN: CN4.1
PA0: CN4.12 U2.7(PA0)
PA1: CN4.11 U2.8(PA1)
PA4: CN4.10 U2.11(PA4)
PA5: CN4.9 U2.12(PA5)
PA6: CN4.6 U2.13(PA6)
PA7: CN4.5 U2.14(PA7)
PA8: CN3.12 U2.18(PA8)
PA9: CN3.8 U2.19(PA9)
PA10: CN3.7 U2.21(PA10)
PA11: CN4.7 U2.22(PA11)
PA12: CN4.8 U2.23(PA12)
PA15: CN3.5 U2.26(PA15)
PB0: CN3.9 U2.15(PB0)
PB1: CN3.6 U2.16(PB1)
PB2: CN3.10 U2.17(PB2)
PB3: CN4.15 SB12.1 U2.27(PB3)
PB4: CN3.15 U2.28(PB4)
PB5: CN3.14 U2.29(PB5)
PB6: CN3.1 U2.30(PB6)
PB7: CN3.2 U2.31(PB7)
PB8: CN3.11 U2.32(PB8)
PB9: CN3.13 U2.1(PB9)
PC6: SB13.1 U2.20(PC6)
T_JTCK: SB5.1 ; port T_JTCK
T_JTMS: U2.24(PA13) ; port T_JTMS
T_NRST: B1.1 C18.2 CN3.3 CN4.3 U2.6(PF2-NRST) U4.1(IO1) ; port T_NRST
NetC3_2: SB7.1 ; port T_MCO
NetC15_2: C15.2 SB8.1 X1.1(X1)
NetC16_2: C16.2 SB9.1 X1.2(X2)
NetLD3_1: LD3.1 R20.1
NetLD3_2: LD3.2 Q2.3(C)
NetQ2_1: Q2.1(B) R21.2 R22.2
NetR15_2: R15.2 SB6.1
NetR22_1: R22.1 SB12.2 SB13.2
NetSB3_1: U2.9(PA2) ; port T_VCP_TX
NetSB4_1: U2.10(PA3) ; port T_VCP_RX
NetSB5_2: SB5.2 SB6.2 U2.25(PA14-BOOT0)
NetSB7_2: SB7.2 SB8.2 U2.2(PC14-OSC32_IN)
NetSB9_2: SB9.2 U2.3(PC15-OSC32_OUT)

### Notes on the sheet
- (near C25) Ceramic capacitor (Low ESR, ESR<1ohm)
- Decoupling capacitors have to be as close as possible from the pin.
- U2 Footprints : LQFP32 and UFQFPN32
  Pad UFQFPN32 connected with Gnd
- (near B1) RST
- RESET FUNCTION
- D0
- D1
- Arduino Connector
- D2
- D4
- D3
- D5
- A4
- A5
- A6
- A7
- D6
- D7
- D8
- D9
- D10
- A0
- A1
- A2
- A3
- AREF
- D12
- D11
- D13
- HW1 between Pins 4 and 5 of CN3. Top face.

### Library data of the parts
B1 = MCD-01335: Subminiature Side Actuated Tact Switch for SMT - KSS series - 2.0 Newtons - Gull wing, SPST; Part_Type: Misc; Manufacturer: C&K; Manufacturer_HQ_COO: Unknown; Part_Preference: Recommended; Partial_Alternate_Internal_Part_Number: MCD-03218; Provided_By: SUBCO; ECCN_US: EAR99; ECCN_EU: NEC; Component_Country_Of_Origin: France; ID: 3435; Order_Code_RS: 793-1689; ShowFields: YES
C13 C18 C25 = MCD-00006: as C7 on sheet Power
C15 C16 = MCD-01374: Capacitor, MLCC, 5.6pF, 50V, NPO, +/- 0.1pF, 0402, T=0,5mm; Manufacturer_Part_Number: CC0402BRNPO9BN5R6; Manufacturer: YAGEO; Part_Preference: Recommended; Provided_By: SUBCO; Component_Country_Of_Origin: China; ID: 3474; ShowFields: YES
C26 = MCD-01356: Capacitor, MLCC, 4.7uF, 6V3, X5R, 20%, 0402, T=0.5mm; Manufacturer_Part_Number: GRM155R60J475ME47; Manufacturer: MURATA; Part_Preference: Recommended; Partial_Alternate_Internal_Part_Number: MCD-04455; ID: 3456; Order_Code_RS: 814-5230; ShowFields: YES; Component_Country_Of_Origin: Japan°°
CN3 CN4 = MCD-01332: Pin header, 15x1, 2,54mm, VR, TH, Height 6mm/6mm; Part_Type: Connector; Manufacturer_Part_Number: 313115S161145; Manufacturer: LYCONN; Alternate_Manufacturer_Part_Number: TSW 115-08-F-S; Alternate_Manufacturer: SAMTEC; Part_Preference: Recommended; Provided_By: SUBCO; Component_Country_Of_Origin: Unknown; ID: 3432; ShowFields: YES
HW1 = MCD-00043: Jumper, 2.54mm, Black, 4.3A, 6.1mm, 5mR; Part_Type: Misc; Manufacturer: SAMTEC; Part_Preference: Recommended; Partial_Alternate_Internal_Part_Number: MCD-01849, MCD-01864, MCD-02388, MCD-03991, MCD-04284, MCD-04580; Manufacturer_HQ_COO: Unknown; Component_Country_Of_Origin: China, Costa Rica, Malaysia, USA, Vietnam; ID: 2551; Order_Code_RS: 158-7784; ShowFields: YES; Alternate_EMS: A
LD3 = MCD-02900: LED, Green, 2V, 20mA, 0603; Manufacturer_Part_Number: 19-213SYGC/S530-E2/5T; Manufacturer: EVERLIGHT; Part_Type: Display; Part_Preference: Recommended; Partial_Alternate_Internal_Part_Number: MCD-00050; Full_Alternate_Internal_Part_Number: MCD-00320; Component_Country_Of_Origin: China; ID: 5016; ShowFields: YES
Q2 = MCD-00073: NPN Bipolar Transistor; Manufacturer: ON SEMICONDUCTOR; Alternate_Manufacturer_Part_Number: MMBT2222LT1G / MMBT2222ALT1G / MMBT2222ALT3G; Part_Preference: Recommended; Partial_Alternate_Internal_Part_Number: MCD-01737, MCD-03305, MCD-02988; Provided_By: SUBCO; ECCN_US: EAR99; ECCN_EU: NEC; Component_Country_Of_Origin: Unknown; ID: 2519; ShowFields: YES
R15 = MCD-00053: as R5 on sheet ST_LINK_V2-1
R20 = MCD-00064: Resistor,510R,0402,1%,1/16W; Manufacturer_Part_Number: RC0402FR-07510RL; Manufacturer: YAGEO; Part_Preference: Recommended; Provided_By: SUBCO; ECCN_US: EAR99; ECCN_EU: NEC; Component_Country_Of_Origin: China; ID: 2525; Order_Code_RS: 1458804; ShowFields: YES
R21 = MCD-00059: as R2 on sheet ST_LINK_V2-1
R22 = MCD-00063: Resistor,47K,0402,1%,1/16W; Manufacturer_Part_Number: RC0402FR-0747KL; Manufacturer: YAGEO; Part_Preference: Recommended; Provided_By: SUBCO; ECCN_US: EAR99; ECCN_EU: NEC; Component_Country_Of_Origin: China; ID: 2528; Order_Code_RS: 9239430; ShowFields: YES
SB5 SB8-SB10 SB13 = MCD-00071: as SB11 on sheet Power
SB6 SB7 SB12 = MCD-00071: as SB1 on sheet ST_LINK_V2-1
U2 = MCD-01738: MCU, ARM Cortex-M0+ 32-bit, 64KB Flash, 8KB RAM, With Crypto; BMS_Part_Number: 9175352; Part_Type: IC; Part_Preference: Recommended; Manufacturer: STMICROELECTRONICS; Manufacturer_HQ_COO: EU; Order_Code_RS: 193-9850; Component_Country_Of_Origin: Taiwan; ShowFields: YES; ID: 3838
U4 = MCD-03501: Diode, ESD TVS, 5V5, 100nA, 10V, 0201; Manufacturer: STMICROELECTRONICS; Part_Preference: Recommended; Component_Country_Of_Origin: Singapore; ID: 5617; ShowFields: YES
X1 = MCD-00091: Crystal 32.768kHz, 6pF, +-20ppm, 50Kohms max, SMD; Part_Type: Crystal_Osc; Manufacturer_Part_Number: NX3215SA-32.768KHz-EXS00A-MU00525; Manufacturer: NDK; BMS_Part_Number: 9157034; Part_Preference: Recommended; ECCN_US: EAR99; ECCN_EU: NEC; Provided_By: SUBCO; Component_Country_Of_Origin: Japan; ID: 2553; ShowFields: YES

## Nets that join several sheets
3V3: Power (JP1.1 SB11.2), ST_LINK_V2-1 (R11.1), STM32G0_microcontroller (CN4.14 R20.2 SB10.2)
3V3_STLK: Power (C7.2 C9.2 U1.5), ST_LINK_V2-1 (13 pins)
5V: Power (7 pins), STM32G0_microcontroller (CN4.4)
5V_USB_CHGR: Power (D3.1), ST_LINK_V2-1 (7 pins)
5V_USB_STLK: Power (D2.1), ST_LINK_V2-1 (C21.2 U5.1)
E5V: Power (5 pins), ST_LINK_V2-1 (D1.1)
GND: Power (16 pins), ST_LINK_V2-1 (34 pins), STM32G0_microcontroller (14 pins)
VDD: Power (JP1.2), STM32G0_microcontroller (C25.2 C26.2 U2.4)
VIN: Power (C24.2 U8.3), STM32G0_microcontroller (CN4.1)
NetC3_2: ST_LINK_V2-1 (C3.2 R7.2), STM32G0_microcontroller (SB7.1)
NetSB3_1: ST_LINK_V2-1 (SB3.1), STM32G0_microcontroller (U2.9)
NetSB4_1: ST_LINK_V2-1 (SB4.1), STM32G0_microcontroller (U2.10)
T_JTCK: ST_LINK_V2-1 (U7.15 U7.26), STM32G0_microcontroller (SB5.1)
T_JTMS: ST_LINK_V2-1 (R19.2 U7.27), STM32G0_microcontroller (U2.24)
T_NRST: ST_LINK_V2-1 (U7.18), STM32G0_microcontroller (6 pins)

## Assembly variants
G031K8: not fitted C3 CN2 R12 SB1 SB2 SB6 SB7 SB12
